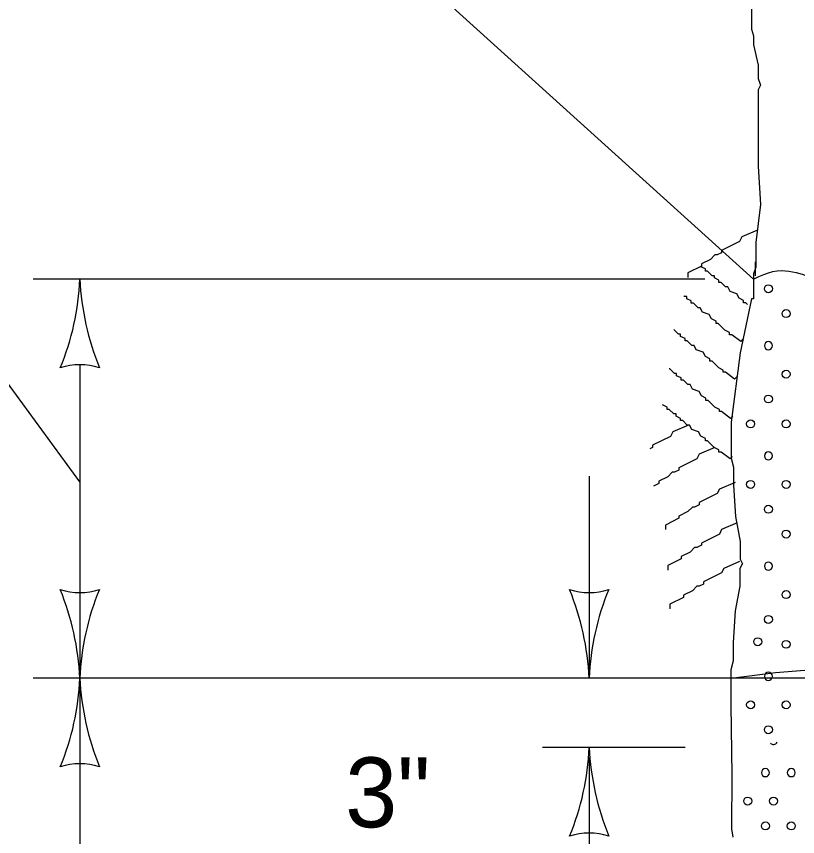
# Model space of a CAD drawing. Extents: x 49991.4 to 50021, y 49987.6 to 50011.4.
# Drawn here: x 50011.243 to 50011.913, y 50001.886 to 50002.59 of the extents above; entities that cross this region are included whole.
import ezdxf

# ---------------------------------------------------------------- set-up
doc = ezdxf.new("R2010")
doc.units = 0
for name, color, linetype in [('Level 1', 7, 'Continuous'), ('Level 2', 7, 'Continuous'), ('Level 3', 7, 'Continuous')]:
    doc.layers.add(name, color=color, linetype=linetype)

msp = doc.modelspace()

# ---------------------------------------------------------------- linework, layer by layer
at = {"layer": 'Level 1'}
for p, q in [((50011.87545745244, 50002.36433985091), (50010.421483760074, 50003.68122201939)), ((50011.87674445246, 50002.379331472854), (50011.87674445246, 50002.367174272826))]:
    msp.add_line(p, q, dxfattribs=at)
for points in [[(50011.87351705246, 50002.61368427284), (50011.87351705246, 50002.57893527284), (50011.87545745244, 50002.57319327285), (50011.87545745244, 50002.56547127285), (50011.879298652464, 50002.54814627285), (50011.879298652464, 50002.53656327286), (50011.88119945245, 50002.53080147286), (50011.879298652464, 50002.52690087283), (50011.879298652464, 50002.467164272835), (50011.879298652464, 50002.46136287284), (50011.88119945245, 50002.42855427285), (50011.87737805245, 50002.39582487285), (50011.87737805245, 50002.37459927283), (50011.87545745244, 50002.36885727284), (50011.87545745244, 50002.355333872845), (50011.87545745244, 50002.34765147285), (50011.87351705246, 50002.34765147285), (50011.86387445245, 50002.30133927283), (50011.85619205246, 50002.24158287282), (50011.85619205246, 50002.21075427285), (50011.858112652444, 50002.20303227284), (50011.858112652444, 50002.187588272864), (50011.86001345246, 50002.160640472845), (50011.86387445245, 50002.139414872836), (50011.86387445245, 50002.12401047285), (50011.86583465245, 50002.12014947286)], [(50011.878823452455, 50002.40641787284), (50011.86530005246, 50002.40063627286), (50011.86337945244, 50002.39675547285), (50011.84797505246, 50002.38905327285), (50011.84797505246, 50002.38715247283), (50011.844153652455, 50002.385192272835), (50011.84217365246, 50002.385192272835), (50011.83831265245, 50002.381331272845), (50011.83061045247, 50002.377470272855), (50011.83061045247, 50002.37558927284), (50011.819027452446, 50002.36978787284), (50011.819027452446, 50002.36592687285)], [(50011.87030945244, 50002.34266187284), (50011.86870565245, 50002.34424587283), (50011.866785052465, 50002.34424587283), (50011.866785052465, 50002.346186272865), (50011.86296365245, 50002.34810687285), (50011.86098365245, 50002.351928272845), (50011.85520205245, 50002.35390827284), (50011.853281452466, 50002.35774947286), (50011.85134105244, 50002.35774947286), (50011.84748005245, 50002.36161047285), (50011.84555945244, 50002.36161047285), (50011.84555945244, 50002.36351127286), (50011.84173805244, 50002.36547147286), (50011.84173805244, 50002.36737227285), (50011.839797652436, 50002.36737227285), (50011.835936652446, 50002.37123327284), (50011.83401605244, 50002.37123327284), (50011.83401605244, 50002.37319347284), (50011.83011545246, 50002.37509427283)], [(50011.866290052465, 50002.31292227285), (50011.86436945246, 50002.31098187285), (50011.85664745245, 50002.31678327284), (50011.85474665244, 50002.31678327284), (50011.85474665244, 50002.31870387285), (50011.85084605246, 50002.32064427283), (50011.845064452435, 50002.32638627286), (50011.84316365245, 50002.32638627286), (50011.84316365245, 50002.32836627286), (50011.83930265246, 50002.330247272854), (50011.837342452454, 50002.334108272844), (50011.831600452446, 50002.33606847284), (50011.82966005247, 50002.33992947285), (50011.827739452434, 50002.33992947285), (50011.82387845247, 50002.34379047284), (50011.82197765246, 50002.34379047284), (50011.82197765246, 50002.34569127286), (50011.818116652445, 50002.34765147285), (50011.818116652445, 50002.34953247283), (50011.81615645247, 50002.34953247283), (50011.81556245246, 50002.35014627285)], [(50011.86098365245, 50002.28062847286), (50011.85902345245, 50002.278668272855), (50011.85134105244, 50002.28448947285), (50011.849420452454, 50002.28448947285), (50011.849420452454, 50002.286390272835), (50011.84555945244, 50002.28835047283), (50011.839797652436, 50002.29411227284), (50011.83783745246, 50002.29411227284), (50011.83783745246, 50002.29603287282), (50011.83401605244, 50002.29797327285), (50011.83209545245, 50002.30183427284), (50011.82625445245, 50002.303794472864), (50011.82435365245, 50002.307615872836), (50011.822433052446, 50002.307615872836), (50011.818532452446, 50002.31143727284), (50011.81665145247, 50002.31143727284), (50011.81665145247, 50002.31339747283), (50011.81279045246, 50002.31533787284), (50011.81279045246, 50002.31725847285), (50011.810850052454, 50002.31725847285), (50011.80698905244, 50002.32113927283)], [(50011.857617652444, 50002.246889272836), (50011.85569705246, 50002.24494887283), (50011.84797505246, 50002.25075027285), (50011.84605445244, 50002.25075027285), (50011.84605445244, 50002.25267087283), (50011.84217365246, 50002.25461127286), (50011.83643165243, 50002.260353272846), (50011.83447145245, 50002.260353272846), (50011.83447145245, 50002.26233327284), (50011.83061045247, 50002.26425387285), (50011.82870965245, 50002.26807527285), (50011.82288845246, 50002.27003547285), (50011.82098765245, 50002.27389647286), (50011.819027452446, 50002.27389647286), (50011.81520605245, 50002.277757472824), (50011.81328545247, 50002.277757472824), (50011.81328545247, 50002.27965827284), (50011.80940465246, 50002.28157887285), (50011.80940465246, 50002.28351927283), (50011.80748405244, 50002.28351927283), (50011.80362305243, 50002.28738027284), (50011.80296965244, 50002.28738027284)], [(50011.857142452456, 50002.212219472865), (50011.85520205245, 50002.21025927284), (50011.84748005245, 50002.21600127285), (50011.84555945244, 50002.21600127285), (50011.84555945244, 50002.21798127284), (50011.84169845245, 50002.21990187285), (50011.835936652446, 50002.22568347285), (50011.83401605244, 50002.22568347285), (50011.83401605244, 50002.22762387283), (50011.83011545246, 50002.229544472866), (50011.82821465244, 50002.233405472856), (50011.822433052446, 50002.23530627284), (50011.82051245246, 50002.23916727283), (50011.818532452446, 50002.23916727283), (50011.814711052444, 50002.243028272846), (50011.81279045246, 50002.243028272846), (50011.81279045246, 50002.24494887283), (50011.80892945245, 50002.246889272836), (50011.80892945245, 50002.24880987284), (50011.80698905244, 50002.24880987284), (50011.80312805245, 50002.25267087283), (50011.801207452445, 50002.25267087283), (50011.801207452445, 50002.25461127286), (50011.797346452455, 50002.256492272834)], [(50011.81952245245, 50002.23916727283), (50011.806038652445, 50002.233405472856), (50011.80407845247, 50002.22950487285), (50011.788674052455, 50002.221822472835), (50011.788674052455, 50002.21986227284), (50011.786456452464, 50002.21877327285)], [(50011.84217365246, 50002.21990187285), (50011.82867005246, 50002.21412027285), (50011.82674945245, 50002.21025927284), (50011.811305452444, 50002.20253727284), (50011.811305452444, 50002.200636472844), (50011.80744445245, 50002.19867627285), (50011.80554365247, 50002.19867627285), (50011.801702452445, 50002.19485487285), (50011.79398045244, 50002.190993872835), (50011.79398045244, 50002.18905347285), (50011.789604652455, 50002.186875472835)], [(50011.85955805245, 50002.19000387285), (50011.84605445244, 50002.18422227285), (50011.844153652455, 50002.18036127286), (50011.82870965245, 50002.17263927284), (50011.82870965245, 50002.17073847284), (50011.82480905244, 50002.16881787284), (50011.82288845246, 50002.16881787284), (50011.819027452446, 50002.164956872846), (50011.811305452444, 50002.161095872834), (50011.811305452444, 50002.15917527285), (50011.79976205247, 50002.15337387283), (50011.79976205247, 50002.14951287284)], [(50011.86143905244, 50002.15531427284), (50011.84797505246, 50002.14955247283), (50011.84605445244, 50002.14569147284), (50011.83061045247, 50002.13796947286), (50011.83061045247, 50002.13600927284), (50011.82674945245, 50002.13410847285), (50011.82480905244, 50002.13410847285), (50011.82098765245, 50002.130267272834), (50011.81326565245, 50002.126406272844), (50011.81326565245, 50002.12446587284), (50011.801702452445, 50002.11868427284), (50011.801702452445, 50002.11482327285)], [(50011.86337945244, 50002.12205027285), (50011.84991545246, 50002.11624887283), (50011.84797505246, 50002.112427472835), (50011.83253105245, 50002.104705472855), (50011.83253105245, 50002.10274527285), (50011.82867005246, 50002.100864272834), (50011.82674945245, 50002.100864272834), (50011.82288845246, 50002.09698347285), (50011.81520605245, 50002.09314227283), (50011.81520605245, 50002.09120187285), (50011.80362305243, 50002.08542027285), (50011.80362305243, 50002.08155927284)], [(50011.857776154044, 50001.88561458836), (50011.85676547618, 50001.892647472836), (50011.85676547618, 50001.892647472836), (50011.85703203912, 50001.938959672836), (50011.85619205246, 50001.99871607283), (50011.85619205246, 50002.02954467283), (50011.858112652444, 50002.03726667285), (50011.858112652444, 50002.05271067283), (50011.86001345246, 50002.07965847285), (50011.86387445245, 50002.10088407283), (50011.86387445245, 50002.11628847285), (50011.86583465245, 50002.12014947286)], [(50011.85619205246, 50002.022033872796), (50011.89405508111, 50002.02690161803), (50011.92652865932, 50002.02956472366)]]:
    msp.add_lwpolyline(points, dxfattribs=at)
for centre, radius in [((50011.88807408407, 50002.35617366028), 0.0034077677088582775), ((50011.88807408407, 50002.35617366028), 0.0034077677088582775), ((50011.90331408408, 50002.33483766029), 0.0034077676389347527), ((50011.90331408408, 50002.28290966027), 0.0034077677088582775), ((50011.88807408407, 50002.26157366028), 0.0034077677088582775), ((50011.88807408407, 50002.26157366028), 0.0034077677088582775), ((50011.87283408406, 50002.24023766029), 0.0034077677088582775), ((50011.90331408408, 50002.24023766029), 0.0034077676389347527), ((50011.87283408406, 50002.18830966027), 0.0034077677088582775), ((50011.90331408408, 50002.18830966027), 0.0034077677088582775), ((50011.88807408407, 50002.16697366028), 0.0034077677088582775), ((50011.88807408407, 50002.16697366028), 0.0034077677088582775), ((50011.90331408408, 50002.145637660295), 0.0034077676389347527), ((50011.90331408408, 50002.09370966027), 0.0034077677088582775), ((50011.88807408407, 50002.07237366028), 0.0034077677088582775), ((50011.88807408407, 50002.07237366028), 0.0034077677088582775), ((50011.878942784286, 50002.05324710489), 0.0034077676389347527), ((50011.90331408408, 50002.05103766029), 0.0034077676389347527), ((50011.87283408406, 50001.99910966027), 0.0034077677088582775), ((50011.90331408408, 50001.99910966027), 0.0034077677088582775), ((50011.88807408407, 50001.97777366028), 0.0034077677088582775), ((50011.88807408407, 50001.97777366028), 0.0034077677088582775), ((50011.87035163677, 50001.91649362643), 0.0034077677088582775), ((50011.892491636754, 50001.91649362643), 0.0034077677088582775), ((50011.885591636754, 50001.89515762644), 0.0034077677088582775), ((50011.90773163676, 50001.89515762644), 0.0034077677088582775)]:
    msp.add_circle(centre, radius, dxfattribs=at)
for centre, radius, start, end in [((50011.88807408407, 50002.30740566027), 0.0034077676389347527, 0, 180), ((50011.88807408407, 50002.307293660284), 0.0034077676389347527, 180, 0), ((50011.88807408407, 50002.307293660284), 0.0034077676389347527, 180, 0), ((50011.88807408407, 50002.212805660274), 0.0034077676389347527, 0, 180), ((50011.88807408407, 50002.21269366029), 0.0034077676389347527, 180, 0), ((50011.88807408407, 50002.21269366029), 0.0034077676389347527, 180, 0), ((50011.88807408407, 50002.11820566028), 0.0034077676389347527, 0, 180), ((50011.88807408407, 50002.11809366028), 0.0034077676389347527, 180, 0), ((50011.88807408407, 50002.11809366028), 0.0034077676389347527, 180, 0), ((50011.88807408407, 50002.02360566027), 0.0034077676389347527, 0, 180), ((50011.88807408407, 50002.02349366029), 0.0034077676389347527, 180, 0), ((50011.88807408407, 50002.02349366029), 0.0034077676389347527, 180, 0), ((50011.892491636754, 50001.96842162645), 0.0034077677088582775, 219.1408893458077, 334.5937855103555), ((50011.885591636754, 50001.94098962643), 0.0034077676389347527, 0, 180), ((50011.90773163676, 50001.94098962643), 0.0034077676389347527, 0, 180), ((50011.885591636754, 50001.940877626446), 0.0034077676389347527, 180, 0), ((50011.90773163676, 50001.940877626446), 0.0034077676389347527, 180, 0)]:
    msp.add_arc(centre, radius, start, end, dxfattribs=at)
msp.add_spline([(50011.87545745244, 50002.36433985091), (50011.875457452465, 50002.36433985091), (50011.92992850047, 50002.36439387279), (50011.987660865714, 50002.360228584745), (50012.105838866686, 50002.36264038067), (50012.12890166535, 50002.362489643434), (50012.180484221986, 50002.36227107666), (50012.21434997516, 50002.36103972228), (50012.26179380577, 50002.36439387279)], degree=3, dxfattribs=at)
at = {"layer": 'Level 3'}
for p, q in [((50011.297482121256, 50002.19046076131), (50011.16107216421, 50002.37660995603)), ((50011.83351705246, 50002.36439387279), (50011.257482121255, 50002.36439387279)), ((50011.29748212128, 50002.29095387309), (50011.297482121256, 50002.0220338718)), ((50011.73437829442, 50002.19543387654), (50011.734378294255, 50002.02203387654)), ((50012.77933849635, 50002.022033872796), (50011.257482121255, 50002.022033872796)), ((50011.297482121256, 50002.022033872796), (50011.297482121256, 50001.62595082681)), ((50011.81670055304, 50001.962541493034), (50011.6943782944, 50001.962541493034)), ((50011.7343782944, 50001.95404149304), (50011.7343782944, 50001.82401777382))]:
    msp.add_line(p, q, dxfattribs=at)
for centre, radius, start, end in [((50011.07534861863, 50002.3735505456), 0.22232214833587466, 337.45601111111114, 357.63951944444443), ((50011.07534861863, 50002.3735505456), 0.22232214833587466, 337.45601111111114, 357.63951944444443), ((50011.53019463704, 50002.37588660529), 0.23299613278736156, 182.8273111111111, 202.0771611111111), ((50011.53019463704, 50002.37588660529), 0.23299613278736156, 182.8273111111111, 202.0771611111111), ((50011.297482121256, 50002.236179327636), 0.054774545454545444, 72.13881944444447, 107.86118055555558), ((50011.297482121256, 50002.236179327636), 0.054774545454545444, 72.13881944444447, 107.86118055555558), ((50011.06476960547, 50002.01054114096), 0.23299613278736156, 2.827311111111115, 22.077161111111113), ((50011.297482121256, 50002.15024841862), 0.054774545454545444, 252.13881944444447, 287.86118055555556), ((50011.51961562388, 50002.01287720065), 0.22232214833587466, 157.45601111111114, 177.63951944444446), ((50011.50166577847, 50002.01054114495), 0.23299613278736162, 2.827311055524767, 22.077161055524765), ((50011.7343782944, 50002.15024842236), 0.054774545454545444, 252.1388193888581, 287.86118049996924), ((50011.95651179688, 50002.01287720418), 0.22232214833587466, 157.45601105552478, 177.6395193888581), ((50011.07534861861, 50002.03119054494), 0.22232214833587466, 337.45601111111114, 357.63951944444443), ((50011.53019463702, 50002.03352660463), 0.23299613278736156, 182.8273111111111, 202.0771611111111), ((50011.512244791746, 50001.97169816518), 0.22232214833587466, 337.45601111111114, 357.63951944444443), ((50011.96709081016, 50001.97403422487), 0.23299613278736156, 182.8273111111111, 202.0771611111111), ((50011.297482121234, 50001.89381932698), 0.054774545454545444, 72.13881944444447, 107.86118055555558), ((50011.73437829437, 50001.83432694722), 0.054774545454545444, 72.13881944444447, 107.86118055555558)]:
    msp.add_arc(centre, radius, start, end, dxfattribs=at)

# ---------------------------------------------------------------- texts
at = {"layer": 'Level 2'}
msp.add_text('3" ', height=0.060000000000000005, dxfattribs=at).set_placement((50011.52508144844, 50001.89401777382))

doc.saveas('drawing.dxf')
